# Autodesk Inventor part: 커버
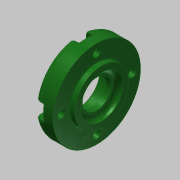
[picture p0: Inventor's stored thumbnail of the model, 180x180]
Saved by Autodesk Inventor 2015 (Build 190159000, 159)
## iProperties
Created: 2015-11
Part Number: 커버
Material: 알루미늄 6061
Document SubType Name: Modeling
Designer: mduedu
Density: 1 g/cm^3
Appearance: 매끄러움 - 짙은 산림 녹색
Author: mduedu
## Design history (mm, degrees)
sketch "스케치1"
  geometry: L1 (-7, 0)-(7, 0); L2 (-7, 0)-(-7, 26); L3 (-7, 26)-(4, 26); L4 (4, 26)-(4, 16); L5 (4, 16)-(7, 16); L6 (7, 16)-(7, 0); 2 further points
  constraints: 12 end point, 3 perpendicular, 2 parallel, 1 coincident, 1 horizontal, 1 midpoint
  dimensions: "d0" = 14 distance of L1.start L1.end; "d1" = 52 diameter of L3 L1; "d2" = 3 distance of L4.end L5.end; "d3" = 32 diameter of L5 L1
revolve "회전1" sketch "스케치1" stored, may be unused: angle "d4" = 90 deg
hole "구멍1" diameter "d7" = 25; stored, may be unused: countersink angle "d11" = 90 deg, drill point angle "d13" = 0 deg; dims "d5" = 10, "d6" = 10, "d8" = 6, "d9" = 4, "d10" = 2, "d12" = 3
hole "구멍2" diameter "d16" = 25; stored, may be unused: countersink angle "d20" = 90 deg, drill point angle "d22" = 0 deg; dims "d17" = 6, "d18" = 4, "d19" = 2, "d21" = 7.7, "d58" = 10, "d59" = 10
hole "구멍3" diameter "d25" = 17; stored, may be unused: countersink angle "d29" = 90 deg, drill point angle "d31" = 0 deg; dims "d23" = 10, "d24" = 10, "d26" = 6, "d27" = 4, "d28" = 2, "d30" = 4.2
chamfer "모따기1" distance "d32" = 0.6; stored, may be unused: second distance "d33" = 2, angle "d34" = 30 deg
fillet "모깎기1" dims "d35" = 0.3
fillet "모깎기2" dims "d36" = 3
fillet "모깎기3" dims "d37" = 3
fillet "모깎기4" dims "d38" = 0.3
sketch "스케치3" dims "d61" = 42
  geometry: C1 r 26 at (0, 0) reference; 2 further points
  constraints: 2 vertical alignment, 1 coincident, 2 other
hole "구멍4" sketch "스케치3" at (0, -21) diameter "d44" = 4.5; stored, may be unused: countersink angle "d48" = 90 deg, drill point angle "d50" = 0 deg; dims "d45" = 6, "d46" = 8, "d47" = 4.6, "d49" = 8
sketch "스케치4"
  geometry: L1 (-4, 0)-(-4, -4.69); L2 (4, 0)-(4, -4.69); A1 r 4 centre (0, 0) between (3.614, -1.714) and (-3.614, -1.714) reference; A2 r 26 centre (0, 21) between (-4, -4.69) and (4, -4.69) reference; 1 further point
  constraints: 4 end point, 4 point on circle, 2 tangent, 1 parallel, 1 vertical
extrude "돌출1" cut sketch "스케치4" stored distance "d51" = 0; taper "d52" = 0 deg
fillet "모깎기5" dims "d56" = 0.3
fillet "모깎기6" dims "d57" = 1
node "솔리드1"
pattern_circular "원형 패턴1" dims angle "d54" = 360 deg
